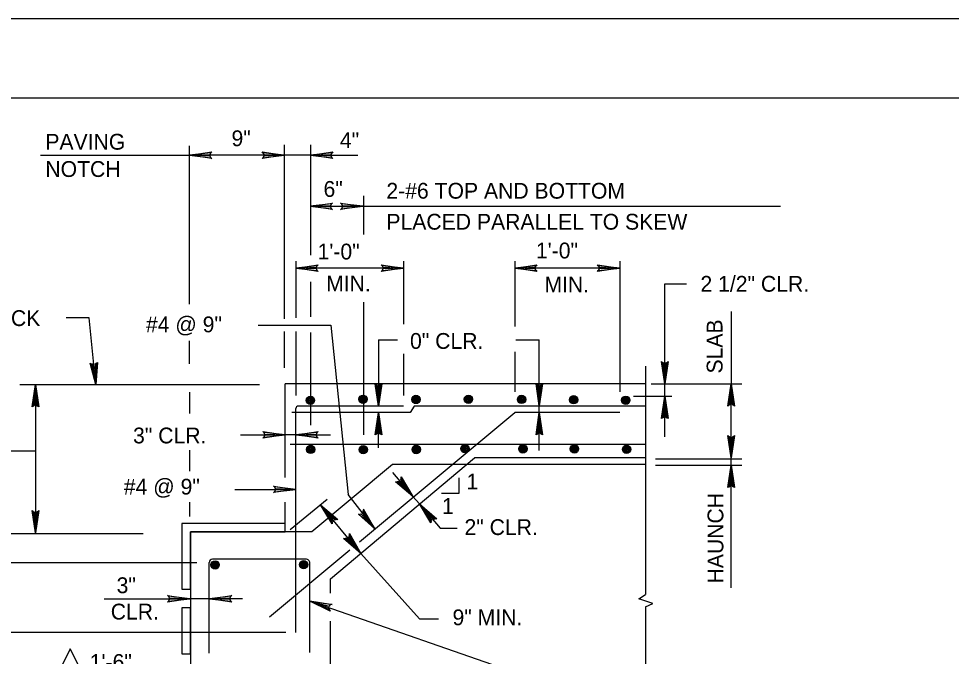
# Model space of a CAD drawing. Extents: x 638653 to 642302, y 298557 to 300414.
# Drawn here: x 639099.6 to 639276.5, y 300217.5 to 300338.5 of the extents above; entities that cross this region are included whole.
import ezdxf

# ---------------------------------------------------------------- set-up
doc = ezdxf.new("R2010")
doc.units = 0
doc.layers.add('1', color=7, linetype='Continuous')
doc.layers.add('PLT-BNDY', color=7, linetype='Continuous')

msp = doc.modelspace()

# ---------------------------------------------------------------- linework, layer by layer
at = {"layer": '1'}
for p, q in [((639022.16, 300323.52), (639808.16, 300323.52)), ((639132.03, 300284.33), (639132.03, 300314.38)), ((639150, 300314.58), (639150, 300281.56)), ((639155, 300314.58), (639155, 300293.63)), ((639103.75, 300312.6), (639132.19, 300312.6)), ((639150, 300312.6), (639132.03, 300312.6)), ((639155, 300312.6), (639150, 300312.6)), ((639155, 300312.6), (639163.93, 300312.6)), ((639165, 300304.9), (639165, 300297.57)), ((639154.89, 300302.91), (639164.89, 300302.91)), ((639164.89, 300302.91), (639244.12, 300302.91)), ((639152.19, 300292.52), (639152.19, 300281.76)), ((639172.6, 300292.52), (639172.6, 300280.52)), ((639193.69, 300292.52), (639193.69, 300280.12)), ((639213.6, 300292.52), (639213.6, 300267.71)), ((639172.6, 300291.17), (639152.19, 300291.17)), ((639213.6, 300291.17), (639193.69, 300291.17)), ((639155, 300288.55), (639155, 300281.96)), ((639222.16, 300288.19), (639226.3, 300288.19)), ((639222.16, 300269.23), (639222.16, 300288.19)), ((639165, 300284.74), (639165, 300259.52)), ((639234.75, 300282.97), (639234.75, 300268.92)), ((639108.62, 300281.8), (639112.97, 300281.8)), ((639114.29, 300269.08), (639113.01, 300281.73)), ((639145.05, 300280.36), (639158.81, 300280.36)), ((639158.81, 300280.36), (639162.12, 300248.19)), ((639150, 300279.17), (639150, 300272.25)), ((639152.19, 300279.17), (639152.19, 300267)), ((639155, 300278.98), (639155, 300261.35)), ((639132.03, 300276.58), (639132.03, 300277.39)), ((639132.03, 300273), (639132.03, 300277.04)), ((639167.86, 300277.54), (639167.86, 300265.01)), ((639167.86, 300277.54), (639171.48, 300277.54)), ((639193.89, 300277.54), (639198.36, 300277.54)), ((639198.36, 300262.48), (639198.36, 300277.54)), ((639172.6, 300274.91), (639172.6, 300267)), ((639193.69, 300275.31), (639193.69, 300267.71)), ((639218.5, 300272.55), (639218.5, 300229.23)), ((639099.82, 300269.08), (639145.31, 300269.08)), ((639102.81, 300269.08), (639102.81, 300240.95)), ((639218.5, 300269.23), (639150.15, 300269.23)), ((639150.15, 300251.43), (639150.15, 300269.23)), ((639219.59, 300269.23), (639236.78, 300269.23)), ((639222.16, 300266.86), (639222.16, 300269.23)), ((639234.75, 300230.91), (639234.75, 300268.92)), ((639132.03, 300267.67), (639132.03, 300263.61)), ((639216.19, 300266.86), (639223.49, 300266.86)), ((639222.16, 300259.14), (639222.16, 300266.86)), ((639173.88, 300263.76), (639151.4, 300263.76)), ((639152.19, 300222.03), (639152.19, 300264.51)), ((639172.6, 300265.01), (639152.69, 300265.01)), ((639164.29, 300239.27), (639193.69, 300263.76)), ((639167.86, 300257.08), (639167.86, 300263.76)), ((639167.86, 300257.67), (639167.86, 300263.76)), ((639174.63, 300265.01), (639173.88, 300263.76)), ((639218.5, 300265.01), (639174.63, 300265.01)), ((639213.6, 300263.76), (639193.69, 300263.76)), ((639198.36, 300256.56), (639198.36, 300261.23)), ((639141.71, 300259.54), (639150.15, 300259.54)), ((639152.19, 300259.54), (639150.15, 300259.54)), ((639152.19, 300259.54), (639158.75, 300259.54)), ((639102.81, 300256.42), (639065.53, 300256.42)), ((639132.03, 300256.61), (639132.03, 300252.66)), ((639218.5, 300257.7), (639151.11, 300257.7)), ((639158.75, 300232.2), (639186.09, 300255.17)), ((639218.5, 300255.17), (639186.09, 300255.17)), ((639220.37, 300255.01), (639236.78, 300255.01)), ((639170.5, 300253.92), (639155.25, 300241.11)), ((639184.6, 300253.92), (639170.5, 300253.92)), ((639218.5, 300253.92), (639184.6, 300253.92)), ((639220.37, 300253.76), (639236.78, 300253.76)), ((639234.75, 300230.48), (639234.75, 300253.76)), ((639170.55, 300252.39), (639174.37, 300247.83)), ((639183.19, 300248.47), (639183.19, 300251.37)), ((639140.63, 300249.2), (639152.19, 300249.2)), ((639167.19, 300241.68), (639162.12, 300248.19)), ((639174.37, 300247.83), (639175.62, 300246.42)), ((639179.81, 300248.47), (639183.19, 300248.47)), ((639132.03, 300246.77), (639132.03, 300244.07)), ((639150.15, 300241.11), (639150.15, 300246.77)), ((639151.09, 300241.58), (639158.12, 300247.36)), ((639164.53, 300237.04), (639156.87, 300246.26)), ((639175.62, 300246.42), (639179.54, 300241.83)), ((639130.59, 300242.71), (639130.59, 300230.23)), ((639150.15, 300242.71), (639130.59, 300242.71)), ((639041.4, 300240.79), (639105.15, 300240.79)), ((639103.9, 300240.79), (639123.26, 300240.79)), ((639150.15, 300241.11), (639132.19, 300241.11)), ((639132.19, 300241.11), (639132.19, 300181.58)), ((639155.25, 300241.11), (639150.15, 300241.11)), ((639179.54, 300241.83), (639182.79, 300241.83)), ((639147.19, 300225.01), (639162.45, 300237.73)), ((639164.53, 300237.04), (639175.64, 300224.6)), ((639093.22, 300235.33), (639133.44, 300235.33)), ((639135.78, 300218.1), (639135.78, 300235.33)), ((639154.06, 300235.95), (639136.4, 300235.95)), ((639154.84, 300218.22), (639154.84, 300235.33)), ((639158.75, 300229.48), (639158.75, 300232.2)), ((639130.59, 300230.23), (639132.19, 300230.23)), ((639115.82, 300228.44), (639131.9, 300228.44)), ((639135.81, 300228.44), (639131.9, 300228.44)), ((639142.09, 300228.44), (639135.81, 300228.44)), ((639132.19, 300226.74), (639130.59, 300226.74)), ((639130.59, 300226.74), (639130.59, 300217.96)), ((639132.19, 300226.68), (639132.19, 300226.74)), ((639200.34, 300212.18), (639154.84, 300227.98)), ((639218.5, 300226.89), (639218.5, 300210.33)), ((639175.64, 300224.6), (639179.27, 300224.6)), ((639158.75, 300181.42), (639158.75, 300224.21)), ((639150.31, 300222.03), (639087.77, 300222.03)), ((639130.59, 300217.96), (639132.19, 300217.96))]:
    msp.add_line(p, q, dxfattribs=at)
for points in [[(639136.09, 300312.13), (639135.94, 300312.44), (639132.03, 300312.6), (639136.09, 300312.13), (639136.25, 300311.97), (639132.03, 300312.6), (639135.94, 300312.76), (639136.09, 300313.07), (639132.03, 300312.6), (639136.25, 300313.22), (639136.09, 300313.07)], [(639136.09, 300312.13), (639135.94, 300312.44), (639132.03, 300312.6), (639136.09, 300312.13), (639136.25, 300311.97), (639132.03, 300312.6), (639135.94, 300312.76), (639136.09, 300313.07), (639132.03, 300312.6), (639136.25, 300313.22), (639136.09, 300313.07)], [(639145.94, 300313.07), (639146.09, 300312.76), (639150, 300312.6), (639145.94, 300313.07), (639145.78, 300313.22), (639150, 300312.6), (639146.09, 300312.44), (639145.94, 300312.13), (639150, 300312.6), (639145.78, 300311.97), (639145.94, 300312.13)], [(639159.06, 300312.13), (639158.9, 300312.44), (639155, 300312.6), (639159.06, 300312.13), (639159.22, 300311.97), (639155, 300312.6), (639158.9, 300312.76), (639159.06, 300313.07), (639155, 300312.6), (639159.22, 300313.22), (639159.06, 300313.07)], [(639158.95, 300302.44), (639158.8, 300302.75), (639154.89, 300302.91), (639158.95, 300302.44), (639159.11, 300302.28), (639154.89, 300302.91), (639158.8, 300303.06), (639158.95, 300303.37), (639154.89, 300302.91), (639159.11, 300303.53), (639158.95, 300303.37)], [(639158.95, 300302.44), (639158.8, 300302.75), (639154.89, 300302.91), (639158.95, 300302.44), (639159.11, 300302.28), (639154.89, 300302.91), (639158.8, 300303.06), (639158.95, 300303.37), (639154.89, 300302.91), (639159.11, 300303.53), (639158.95, 300303.37)], [(639160.83, 300303.37), (639160.98, 300303.06), (639164.89, 300302.91), (639160.83, 300303.37), (639160.67, 300303.53), (639164.89, 300302.91), (639160.98, 300302.75), (639160.83, 300302.44), (639164.89, 300302.91), (639160.67, 300302.28), (639160.83, 300302.44)], [(639156.25, 300290.7), (639156.09, 300291.02), (639152.19, 300291.17), (639156.25, 300290.7), (639156.4, 300290.55), (639152.19, 300291.17), (639156.09, 300291.33), (639156.25, 300291.64), (639152.19, 300291.17), (639156.4, 300291.8), (639156.25, 300291.64)], [(639168.53, 300291.64), (639168.69, 300291.33), (639172.6, 300291.17), (639168.53, 300291.64), (639168.38, 300291.8), (639172.6, 300291.17), (639168.69, 300291.02), (639168.53, 300290.7), (639172.6, 300291.17), (639168.38, 300290.55), (639168.53, 300290.7)], [(639197.75, 300290.7), (639197.59, 300291.02), (639193.69, 300291.17), (639197.75, 300290.7), (639197.9, 300290.55), (639193.69, 300291.17), (639197.59, 300291.33), (639197.75, 300291.64), (639193.69, 300291.17), (639197.9, 300291.8), (639197.75, 300291.64)], [(639209.53, 300291.64), (639209.69, 300291.33), (639213.6, 300291.17), (639209.53, 300291.64), (639209.38, 300291.8), (639213.6, 300291.17), (639209.69, 300291.02), (639209.53, 300290.7), (639213.6, 300291.17), (639209.38, 300290.55), (639209.53, 300290.7)], [(639114.45, 300273.14), (639114.14, 300272.98), (639114.29, 300269.08), (639114.45, 300273.14), (639114.6, 300273.29), (639114.29, 300269.08), (639113.67, 300272.98), (639113.35, 300272.98), (639114.29, 300269.08), (639113.2, 300273.14), (639113.35, 300272.98)], [(639114.45, 300273.14), (639114.14, 300272.98), (639114.29, 300269.08), (639114.45, 300273.14), (639114.6, 300273.29), (639114.29, 300269.08), (639113.67, 300272.98), (639113.35, 300272.98), (639114.29, 300269.08), (639113.2, 300273.14), (639113.35, 300272.98)], [(639222.63, 300273.29), (639222.31, 300273.14), (639222.16, 300269.23), (639222.63, 300273.29), (639222.78, 300273.45), (639222.16, 300269.23), (639222, 300273.14), (639221.69, 300273.29), (639222.16, 300269.23), (639221.53, 300273.45), (639221.69, 300273.29)], [(639102.34, 300265.01), (639102.65, 300265.17), (639102.81, 300269.08), (639102.34, 300265.01), (639102.19, 300264.86), (639102.81, 300269.08), (639102.97, 300265.17), (639103.28, 300265.01), (639102.81, 300269.08), (639103.44, 300264.86), (639103.28, 300265.01)], [(639102.34, 300265.01), (639102.65, 300265.17), (639102.81, 300269.08), (639102.34, 300265.01), (639102.19, 300264.86), (639102.81, 300269.08), (639102.97, 300265.17), (639103.28, 300265.01), (639102.81, 300269.08), (639103.44, 300264.86), (639103.28, 300265.01)], [(639168.33, 300269.08), (639168.01, 300268.92), (639167.86, 300265.01), (639168.33, 300269.08), (639168.48, 300269.23), (639167.86, 300265.01), (639167.7, 300268.92), (639167.39, 300269.08), (639167.86, 300265.01), (639167.23, 300269.23), (639167.39, 300269.08)], [(639198.83, 300269.08), (639198.52, 300268.93), (639198.36, 300265.02), (639198.83, 300269.08), (639198.99, 300269.24), (639198.36, 300265.02), (639198.2, 300268.93), (639197.89, 300269.08), (639198.36, 300265.02), (639197.74, 300269.24), (639197.89, 300269.08)], [(639234.28, 300265.17), (639234.59, 300265.33), (639234.75, 300269.23), (639234.28, 300265.17), (639234.12, 300265.01), (639234.75, 300269.23), (639234.9, 300265.33), (639235.21, 300265.17), (639234.75, 300269.23), (639235.37, 300265.01), (639235.21, 300265.17)], [(639221.69, 300262.8), (639222, 300262.95), (639222.16, 300266.86), (639221.69, 300262.8), (639221.53, 300262.64), (639222.16, 300266.86), (639222.31, 300262.95), (639222.63, 300262.8), (639222.16, 300266.86), (639222.78, 300262.64), (639222.63, 300262.8)], [(639167.39, 300259.7), (639167.7, 300259.86), (639167.86, 300263.76), (639167.39, 300259.7), (639167.23, 300259.54), (639167.86, 300263.76), (639168.01, 300259.86), (639168.33, 300259.7), (639167.86, 300263.76), (639168.48, 300259.54), (639168.33, 300259.7)], [(639197.89, 300259.7), (639198.2, 300259.86), (639198.36, 300263.76), (639197.89, 300259.7), (639197.74, 300259.54), (639198.36, 300263.76), (639198.52, 300259.86), (639198.83, 300259.7), (639198.36, 300263.76), (639198.99, 300259.54), (639198.83, 300259.7)], [(639146.09, 300260.01), (639146.25, 300259.7), (639150.15, 300259.54), (639146.09, 300260.01), (639145.94, 300260.17), (639150.15, 300259.54), (639146.25, 300259.39), (639146.09, 300259.08), (639150.15, 300259.54), (639145.94, 300258.92), (639146.09, 300259.08)], [(639156.25, 300259.08), (639156.09, 300259.39), (639152.19, 300259.54), (639156.25, 300259.08), (639156.4, 300258.92), (639152.19, 300259.54), (639156.09, 300259.7), (639156.25, 300260.01), (639152.19, 300259.54), (639156.4, 300260.17), (639156.25, 300260.01)], [(639235.21, 300259.23), (639234.9, 300259.08), (639234.75, 300255.17), (639235.21, 300259.23), (639235.37, 300259.39), (639234.75, 300255.17), (639234.59, 300259.08), (639234.28, 300259.23), (639234.75, 300255.17), (639234.12, 300259.39), (639234.28, 300259.23)], [(639234.28, 300249.7), (639234.59, 300249.86), (639234.75, 300253.76), (639234.28, 300249.7), (639234.12, 300249.54), (639234.75, 300253.76), (639234.9, 300249.86), (639235.21, 300249.7), (639234.75, 300253.76), (639235.37, 300249.54), (639235.21, 300249.7)], [(639172.19, 300251.26), (639172.03, 300250.95), (639174.37, 300247.83), (639172.19, 300251.26), (639172.19, 300251.58), (639174.37, 300247.83), (639171.72, 300250.64), (639171.4, 300250.64), (639174.37, 300247.83), (639171.09, 300250.64), (639171.4, 300250.64)], [(639148.12, 300249.67), (639148.28, 300249.35), (639152.19, 300249.2), (639148.12, 300249.67), (639147.97, 300249.82), (639152.19, 300249.2), (639148.28, 300249.04), (639148.12, 300248.73), (639152.19, 300249.2), (639147.97, 300248.57), (639148.12, 300248.73)], [(639159.06, 300242.83), (639159.22, 300243.14), (639156.87, 300246.26), (639159.06, 300242.83), (639159.06, 300242.67), (639156.87, 300246.26), (639159.53, 300243.45), (639159.84, 300243.45), (639156.87, 300246.26), (639160.15, 300243.45), (639159.84, 300243.45)], [(639177.81, 300242.98), (639177.97, 300243.29), (639175.62, 300246.42), (639177.81, 300242.98), (639177.81, 300242.83), (639175.62, 300246.42), (639178.28, 300243.61), (639178.59, 300243.61), (639175.62, 300246.42), (639178.9, 300243.61), (639178.59, 300243.61)], [(639177.81, 300242.98), (639177.97, 300243.29), (639175.62, 300246.42), (639177.81, 300242.98), (639177.81, 300242.83), (639175.62, 300246.42), (639178.28, 300243.61), (639178.59, 300243.61), (639175.62, 300246.42), (639178.9, 300243.61), (639178.59, 300243.61)], [(639103.28, 300245.01), (639102.97, 300244.86), (639102.81, 300240.95), (639103.28, 300245.01), (639103.44, 300245.17), (639102.81, 300240.95), (639102.65, 300244.86), (639102.34, 300245.01), (639102.81, 300240.95), (639102.19, 300245.17), (639102.34, 300245.01)], [(639164.2, 300244.45), (639164.53, 300244.55), (639167.19, 300241.68), (639164.2, 300244.45), (639164.05, 300244.48), (639167.19, 300241.68), (639164.9, 300244.8), (639164.96, 300245.11), (639167.19, 300241.68), (639165.01, 300245.41), (639164.96, 300245.11)], [(639132.19, 300230.23), (639132.19, 300241.11), (639150.15, 300241.11), (639150.15, 300242.71)], [(639162.34, 300240.48), (639162.19, 300240.17), (639164.53, 300237.04), (639162.34, 300240.48), (639162.34, 300240.79), (639164.53, 300237.04), (639161.87, 300239.86), (639161.56, 300239.86), (639164.53, 300237.04), (639161.25, 300239.86), (639161.56, 300239.86)], [(639128.02, 300228.91), (639128.18, 300228.6), (639132.08, 300228.44), (639128.02, 300228.91), (639127.86, 300229.07), (639132.08, 300228.44), (639128.18, 300228.29), (639128.02, 300227.98), (639132.08, 300228.44), (639127.86, 300227.82), (639128.02, 300227.98)], [(639139.87, 300227.98), (639139.71, 300228.29), (639135.81, 300228.44), (639139.87, 300227.98), (639140.03, 300227.82), (639135.81, 300228.44), (639139.71, 300228.6), (639139.87, 300228.91), (639135.81, 300228.44), (639140.03, 300229.07), (639139.87, 300228.91)], [(639218.5, 300226.89), (639219.9, 300227.51), (639217.25, 300228.45), (639218.5, 300229.23)], [(639132.19, 300217.96), (639132.19, 300226.74)], [(639158.58, 300226.39), (639158.43, 300226.7), (639154.84, 300227.98), (639158.58, 300226.39), (639158.73, 300226.08), (639154.84, 300227.98), (639158.58, 300227.02), (639158.74, 300227.33), (639154.84, 300227.98), (639159.06, 300227.32), (639158.74, 300227.33)]]:
    msp.add_lwpolyline(points, dxfattribs=at)
msp.add_lwpolyline([(639106.99, 300214.07), (639111.83, 300214.07), (639109.41, 300218.91)], close=True, dxfattribs=at)
for centre, radius in [((639164.92, 300266.31), 0.791), ((639164.92, 300266.31), 0.659), ((639174.97, 300266.25), 0.791), ((639184.92, 300266.29), 0.791), ((639194.99, 300266.27), 0.791), ((639204.88, 300266.19), 0.791), ((639154.96, 300266.09), 0.791), ((639154.96, 300266.09), 0.659), ((639154.96, 300266.09), 0.527), ((639154.96, 300266.09), 0.396), ((639154.96, 300266.09), 0.264), ((639154.96, 300266.09), 0.132), ((639164.92, 300266.31), 0.527), ((639164.92, 300266.31), 0.396), ((639164.92, 300266.31), 0.264), ((639164.92, 300266.31), 0.132), ((639174.97, 300266.25), 0.659), ((639174.97, 300266.25), 0.527), ((639174.97, 300266.25), 0.396), ((639174.97, 300266.25), 0.264), ((639174.97, 300266.25), 0.132), ((639184.92, 300266.29), 0.659), ((639184.92, 300266.29), 0.527), ((639184.92, 300266.29), 0.396), ((639184.92, 300266.29), 0.264), ((639184.92, 300266.29), 0.132), ((639194.99, 300266.27), 0.659), ((639194.99, 300266.27), 0.527), ((639194.99, 300266.27), 0.396), ((639194.99, 300266.27), 0.264), ((639194.99, 300266.27), 0.132), ((639204.88, 300266.19), 0.659), ((639204.88, 300266.19), 0.527), ((639204.88, 300266.19), 0.396), ((639204.88, 300266.19), 0.264), ((639204.88, 300266.19), 0.132), ((639214.76, 300266.11), 0.791), ((639214.76, 300266.11), 0.659), ((639214.76, 300266.11), 0.527), ((639214.76, 300266.11), 0.396), ((639214.76, 300266.11), 0.264), ((639214.76, 300266.11), 0.132), ((639155, 300256.78), 0.791), ((639155, 300256.78), 0.659), ((639155, 300256.78), 0.527), ((639155, 300256.78), 0.396), ((639155, 300256.78), 0.264), ((639155, 300256.78), 0.132), ((639164.98, 300256.73), 0.791), ((639164.98, 300256.73), 0.659), ((639164.98, 300256.73), 0.527), ((639164.98, 300256.73), 0.396), ((639164.98, 300256.73), 0.264), ((639164.98, 300256.73), 0.132), ((639175.02, 300256.76), 0.791), ((639175.02, 300256.76), 0.659), ((639175.02, 300256.76), 0.527), ((639175.02, 300256.76), 0.396), ((639175.02, 300256.76), 0.264), ((639175.02, 300256.76), 0.132), ((639184.25, 300256.92), 0.791), ((639184.25, 300256.92), 0.659), ((639184.25, 300256.92), 0.527), ((639184.25, 300256.92), 0.396), ((639184.25, 300256.92), 0.264), ((639184.25, 300256.92), 0.132), ((639195.25, 300256.88), 0.791), ((639195.25, 300256.88), 0.659), ((639195.25, 300256.88), 0.527), ((639195.25, 300256.88), 0.396), ((639195.25, 300256.88), 0.264), ((639195.25, 300256.88), 0.132), ((639205.02, 300256.88), 0.791), ((639205.02, 300256.88), 0.659), ((639205.02, 300256.88), 0.527), ((639205.02, 300256.88), 0.396), ((639205.02, 300256.88), 0.264), ((639205.02, 300256.88), 0.132), ((639214.9, 300256.8), 0.791), ((639214.9, 300256.8), 0.659), ((639214.9, 300256.8), 0.527), ((639214.9, 300256.8), 0.396), ((639214.9, 300256.8), 0.264), ((639214.9, 300256.8), 0.132), ((639136.87, 300234.86), 0.791), ((639136.87, 300234.86), 0.659), ((639136.87, 300234.86), 0.527), ((639136.87, 300234.86), 0.396), ((639153.68, 300234.91), 0.791), ((639153.68, 300234.91), 0.659), ((639153.68, 300234.91), 0.527), ((639153.68, 300234.91), 0.396), ((639153.68, 300234.91), 0.264), ((639136.87, 300234.86), 0.264), ((639136.87, 300234.86), 0.132), ((639153.68, 300234.91), 0.132)]:
    msp.add_circle(centre, radius, dxfattribs=at)
for centre, radius, start, end in [((639152.69, 300264.51), 0.5, 90, 180), ((639136.4, 300235.33), 0.625, 90, 180), ((639154.12, 300235.22), 0.738, 2.021, 92.7509)]:
    msp.add_arc(centre, radius, start, end, dxfattribs=at)
at = {"layer": 'PLT-BNDY'}
msp.add_lwpolyline([(638982.16, 300338.52), (639823.16, 300338.52), (639823.16, 299744.52), (638982.16, 299744.52)], close=True, dxfattribs=at)

# ---------------------------------------------------------------- texts
at = {"layer": '1'}
for s, p in [('PAVING', (639104.69, 300313.66)), ('9"', (639139.99, 300314.32)), ('4"', (639160.55, 300313.97)), ('NOTCH', (639104.69, 300308.48)), ('6"', (639157.44, 300304.7)), ('2-#6 TOP AND BOTTOM', (639169.36, 300304.36)), ('PLACED PARALLEL TO SKEW', (639169.36, 300298.48)), ('1\'-0"', (639156.31, 300292.82)), ('2 1/2" CLR.', (639228.92, 300286.7)), ('TOP OF DECK', (639076.55, 300280.19)), ('#4 @ 9"', (639123.76, 300279)), ('0" CLR.', (639173.84, 300275.86)), ('3" CLR.', (639121.32, 300257.92)), ('#4 @ 9"', (639119.57, 300248.21)), ('1', (639184.55, 300249.18)), ('1', (639179.91, 300244.54)), ('2" CLR.', (639184.17, 300240.53)), (' 3"', (639117.09, 300229.5)), ('CLR.', (639117.09, 300224.5)), ('9" MIN.', (639181.9, 300223.41)), ('1\'-6"', (639113.11, 300214.94))]:
    msp.add_text(s, height=3, dxfattribs=at).set_placement(p)
for s, rotation, p in [('1\'-0"', 360, (639197.71, 300293.02)), ('MIN.', 360, (639157.93, 300286.77)), ('MIN.', 360, (639199.33, 300286.57)), ('SLAB', 90, (639233.1, 300271.18)), ('HAUNCH', 90, (639233.26, 300231.34))]:
    msp.add_text(s, height=3, rotation=rotation, dxfattribs=at).set_placement(p)

doc.saveas('drawing.dxf')
